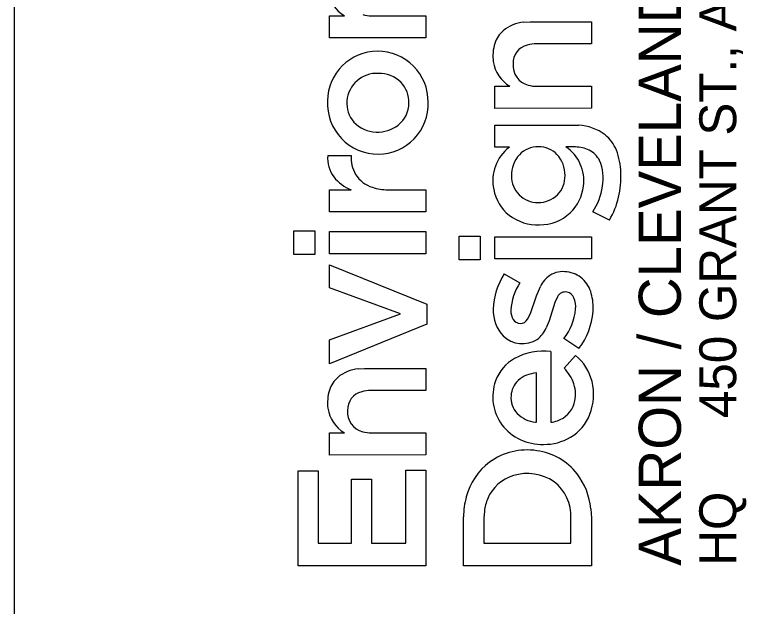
# Model space of a CAD drawing. Extents: x -0.3 to 34, y 0 to 22.
# Drawn here: x 32 to 32.989, y 2.583 to 3.382 of the extents above; entities that cross this region are included whole.
import ezdxf

# ---------------------------------------------------------------- set-up
doc = ezdxf.new("R2010")
doc.units = 0
doc.layers.add('GM_X_Adjacent_County_Text', color=7, linetype='Continuous')
doc.layers.add('GM_X_County', color=7, linetype='Continuous')

msp = doc.modelspace()

# ---------------------------------------------------------------- linework, layer by layer
at = {"layer": 'GM_X_Adjacent_County_Text'}
for p, q in [((32.42542, 3.38066), (32.44552, 3.38071)), ((32.42542, 3.35086), (32.42542, 3.38066)), ((32.48222, 3.38071), (32.55569, 3.38071)), ((32.55569, 3.38071), (32.55571, 3.35096)), ((32.68784, 3.3722), (32.69634, 3.37266)), ((32.69634, 3.37266), (32.77916, 3.37266)), ((32.77916, 3.37266), (32.77917, 3.34287)), ((32.55571, 3.35096), (32.42542, 3.35086)), ((32.77917, 3.34287), (32.70485, 3.3428)), ((32.64888, 3.2855), (32.66897, 3.28555)), ((32.64888, 3.25569), (32.64888, 3.2855)), ((32.70568, 3.28555), (32.77915, 3.28555)), ((32.77915, 3.28555), (32.77917, 3.25579)), ((32.77917, 3.25579), (32.64888, 3.25569)), ((32.6489, 3.20336), (32.64889, 3.23322)), ((32.64889, 3.23322), (32.75236, 3.23322)), ((32.75236, 3.23322), (32.76191, 3.23285)), ((32.66836, 3.20336), (32.6489, 3.20336)), ((32.75763, 3.20356), (32.74487, 3.20361)), ((32.42299, 3.19193), (32.45454, 3.19193)), ((32.42542, 3.14577), (32.45473, 3.14579)), ((32.42542, 3.11593), (32.42542, 3.14577)), ((32.50413, 3.14581), (32.55571, 3.14573)), ((32.55571, 3.14573), (32.55565, 3.11593)), ((32.55565, 3.11593), (32.42542, 3.11593)), ((32.8036, 3.10491), (32.7812, 3.11598)), ((32.37705, 3.05818), (32.37705, 3.09026)), ((32.37705, 3.09026), (32.40543, 3.09026)), ((32.40543, 3.09026), (32.40543, 3.05818)), ((32.42542, 3.05942), (32.42542, 3.08928)), ((32.42542, 3.08928), (32.55571, 3.08928)), ((32.55571, 3.08928), (32.55571, 3.05942)), ((32.60051, 3.05111), (32.60051, 3.08319)), ((32.60051, 3.08319), (32.62889, 3.08319)), ((32.62889, 3.08319), (32.62889, 3.05111)), ((32.64888, 3.05234), (32.64888, 3.0822)), ((32.64888, 3.0822), (32.77917, 3.0822)), ((32.77917, 3.0822), (32.77917, 3.05234)), ((32.40543, 3.05818), (32.37705, 3.05818)), ((32.55571, 3.05942), (32.42542, 3.05942)), ((32.62889, 3.05111), (32.60051, 3.05111)), ((32.77917, 3.05234), (32.64888, 3.05234)), ((32.42542, 3.01327), (32.42542, 3.0446)), ((32.42542, 3.0446), (32.5567, 2.9913)), ((32.66151, 3.03207), (32.68268, 3.02025)), ((32.70483, 3.00258), (32.71036, 3.01526)), ((32.52117, 2.97798), (32.42542, 3.01327)), ((32.69675, 2.97868), (32.70483, 3.00258)), ((32.73342, 3.00101), (32.72985, 2.9933)), ((32.5567, 2.9913), (32.5567, 2.96441)), ((32.72985, 2.9933), (32.72213, 2.96882)), ((32.42542, 2.94294), (32.52117, 2.97798)), ((32.69299, 2.97117), (32.69675, 2.97868)), ((32.72213, 2.96882), (32.71822, 2.95921)), ((32.5567, 2.96441), (32.42542, 2.91086)), ((32.42542, 2.91086), (32.42542, 2.94294)), ((32.76214, 2.93141), (32.74198, 2.94469)), ((32.72453, 2.92747), (32.72463, 2.83195)), ((32.74228, 2.90465), (32.75768, 2.922)), ((32.46439, 2.90397), (32.47289, 2.90443)), ((32.47289, 2.90443), (32.55571, 2.90443)), ((32.55571, 2.90443), (32.55571, 2.87465)), ((32.70489, 2.83182), (32.70489, 2.89834)), ((32.55571, 2.87465), (32.4814, 2.87457)), ((32.70361, 2.83165), (32.70489, 2.83182)), ((32.42542, 2.81728), (32.44552, 2.81733)), ((32.42542, 2.78747), (32.42542, 2.81728)), ((32.48222, 2.81733), (32.55569, 2.81733)), ((32.55569, 2.81733), (32.55571, 2.78756)), ((32.55571, 2.78756), (32.42542, 2.78747)), ((32.38298, 2.63791), (32.38298, 2.76598)), ((32.38298, 2.76598), (32.41012, 2.76598)), ((32.41012, 2.76598), (32.41012, 2.66827)), ((32.52857, 2.66827), (32.52857, 2.76722)), ((32.52857, 2.76722), (32.55571, 2.76722)), ((32.55571, 2.76722), (32.55571, 2.63791)), ((32.45503, 2.66827), (32.45503, 2.75488)), ((32.45503, 2.75488), (32.48218, 2.75488)), ((32.48218, 2.75488), (32.48218, 2.66827)), ((32.63465, 2.71178), (32.63407, 2.7023)), ((32.77847, 2.71497), (32.77917, 2.7021)), ((32.60643, 2.63799), (32.60644, 2.704)), ((32.63407, 2.7023), (32.63407, 2.66838)), ((32.75149, 2.66834), (32.75153, 2.70239)), ((32.77917, 2.7021), (32.77917, 2.638)), ((32.41012, 2.66827), (32.45503, 2.66827)), ((32.48218, 2.66827), (32.52857, 2.66827)), ((32.63407, 2.66838), (32.75149, 2.66834)), ((32.55571, 2.63791), (32.38298, 2.63791)), ((32.77917, 2.638), (32.60643, 2.63799))]:
    msp.add_line(p, q, dxfattribs=at)
for points in [[(32.42542, 3.35086), (32.42542, 3.38066), (32.44552, 3.38071)], [(32.48222, 3.38071), (32.55569, 3.38071), (32.55571, 3.35096), (32.42542, 3.35086)], [(32.68784, 3.3722), (32.69634, 3.37266), (32.77916, 3.37266), (32.77917, 3.34287), (32.70485, 3.3428)], [(32.64888, 3.25569), (32.64888, 3.2855), (32.66897, 3.28555)], [(32.70568, 3.28555), (32.77915, 3.28555), (32.77917, 3.25579), (32.64888, 3.25569)], [(32.66836, 3.20336), (32.6489, 3.20336), (32.64889, 3.23322), (32.75236, 3.23322), (32.76191, 3.23285)], [(32.75763, 3.20356), (32.74487, 3.20361)], [(32.42299, 3.19193), (32.45454, 3.19193)], [(32.50413, 3.14581), (32.55571, 3.14573), (32.55565, 3.11593), (32.42542, 3.11593)], [(32.42542, 3.11593), (32.42542, 3.14577), (32.45473, 3.14579)], [(32.8036, 3.10491), (32.7812, 3.11598)], [(32.66151, 3.03207), (32.68268, 3.02025)], [(32.69299, 2.97117), (32.69675, 2.97868), (32.70483, 3.00258), (32.71036, 3.01526)], [(32.73342, 3.00101), (32.72985, 2.9933), (32.72213, 2.96882), (32.71822, 2.95921)], [(32.76214, 2.93141), (32.74198, 2.94469)], [(32.72453, 2.92747), (32.72463, 2.83195)], [(32.74228, 2.90465), (32.75768, 2.922)], [(32.46439, 2.90397), (32.47289, 2.90443), (32.55571, 2.90443), (32.55571, 2.87465), (32.4814, 2.87457)], [(32.70361, 2.83165), (32.70489, 2.83182), (32.70489, 2.89834)], [(32.42542, 2.78747), (32.42542, 2.81728), (32.44552, 2.81733)], [(32.48222, 2.81733), (32.55569, 2.81733), (32.55571, 2.78756), (32.42542, 2.78747)], [(32.77847, 2.71497), (32.77917, 2.7021), (32.77917, 2.638), (32.60643, 2.63799)], [(32.63465, 2.71178), (32.63407, 2.7023), (32.63407, 2.66838), (32.75149, 2.66834), (32.75153, 2.70239)], [(32.60643, 2.63799), (32.60644, 2.704)]]:
    msp.add_lwpolyline(points, dxfattribs=at)
for points in [[(32.37705, 3.05818), (32.37705, 3.09026), (32.40543, 3.09026), (32.40543, 3.05818)], [(32.42542, 3.05942), (32.42542, 3.08928), (32.55571, 3.08928), (32.55571, 3.05942)], [(32.60051, 3.05111), (32.60051, 3.08319), (32.62889, 3.08319), (32.62889, 3.05111)], [(32.64888, 3.05234), (32.64888, 3.0822), (32.77917, 3.0822), (32.77917, 3.05234)], [(32.42542, 2.91086), (32.42542, 2.94294), (32.52117, 2.97798), (32.42542, 3.01327), (32.42542, 3.0446), (32.5567, 2.9913), (32.5567, 2.96441)], [(32.38298, 2.63791), (32.38298, 2.76598), (32.41012, 2.76598), (32.41012, 2.66827), (32.45503, 2.66827), (32.45503, 2.75488), (32.48218, 2.75488), (32.48218, 2.66827), (32.52857, 2.66827), (32.52857, 2.76722), (32.55571, 2.76722), (32.55571, 2.63791)]]:
    msp.add_lwpolyline(points, close=True, dxfattribs=at)
for centre, radius, start, end in [((32.47027, 3.42141), 0.04763, 188.96462, 238.69865), ((32.47027, 3.42141), 0.04763, 188.96462, 238.69865), ((32.48183, 3.42286), 0.04215, 254.08913, 270.52838), ((32.48183, 3.42286), 0.04215, 254.08913, 270.52838), ((32.69216, 3.32251), 0.04988, 94.97056, 130.22484), ((32.69216, 3.32251), 0.04988, 94.97056, 130.22484), ((32.68694, 3.33085), 0.04016, 132.22383, 161.68229), ((32.68694, 3.33085), 0.04016, 132.22383, 161.68229), ((32.70217, 3.32642), 0.05602, 162.27398, 187.79173), ((32.70217, 3.32642), 0.05602, 162.27398, 187.79173), ((32.70453, 3.29679), 0.04601, 89.60515, 105.33026), ((32.70453, 3.29679), 0.04601, 89.60515, 105.33026), ((32.49014, 3.26543), 0.0674, 89.84756, 179.64047), ((32.49014, 3.26543), 0.0674, 89.84756, 179.64047), ((32.49057, 3.26474), 0.0681, 359.54009, 90.21138), ((32.49057, 3.26474), 0.0681, 359.54009, 90.21138), ((32.69828, 3.31689), 0.02498, 103.68683, 182.21395), ((32.69828, 3.31689), 0.02498, 103.68683, 182.21395), ((32.69372, 3.32624), 0.04763, 188.96462, 238.69865), ((32.69372, 3.32624), 0.04763, 188.96462, 238.69865), ((32.7008, 3.31381), 0.02757, 175.58441, 255.13816), ((32.7008, 3.31381), 0.02757, 175.58441, 255.13816), ((32.48923, 3.26263), 0.0404, 87.04809, 175.57259), ((32.48923, 3.26263), 0.0404, 87.04809, 175.57259), ((32.49204, 3.25999), 0.04299, 45.84264, 90.98008), ((32.49204, 3.25999), 0.04299, 45.84264, 90.98008), ((32.49458, 3.26421), 0.03821, 357.88569, 44.15902), ((32.49458, 3.26421), 0.03821, 357.88569, 44.15902), ((32.70529, 3.32769), 0.04215, 254.08913, 270.52838), ((32.70529, 3.32769), 0.04215, 254.08913, 270.52838), ((32.49083, 3.26209), 0.06819, 176.8344, 270.40384), ((32.49083, 3.26209), 0.06819, 176.8344, 270.40384), ((32.48729, 3.2625), 0.03848, 175.15378, 221.14706), ((32.48729, 3.2625), 0.03848, 175.15378, 221.14706), ((32.49123, 3.26139), 0.06749, 270.06243, 2.37759), ((32.49123, 3.26139), 0.06749, 270.06243, 2.37759), ((32.49446, 3.26318), 0.0383, 308.28936, 359.43468), ((32.49446, 3.26318), 0.0383, 308.28936, 359.43468), ((32.48919, 3.26607), 0.04228, 223.09994, 268.80895), ((32.48919, 3.26607), 0.04228, 223.09994, 268.80895), ((32.49096, 3.2679), 0.04418, 266.56515, 308.06078), ((32.49096, 3.2679), 0.04418, 266.56515, 308.06078), ((32.75907, 3.16789), 0.06503, 53.40344, 87.49062), ((32.75907, 3.16789), 0.06503, 53.40344, 87.49062), ((32.76517, 3.18039), 0.05141, 21.60748, 50.5577), ((32.76517, 3.18039), 0.05141, 21.60748, 50.5577), ((32.70292, 3.15813), 0.05692, 127.37482, 192.22468), ((32.70292, 3.15813), 0.05692, 127.37482, 192.22468), ((32.70693, 3.16927), 0.0346, 88.47302, 136.42562), ((32.70693, 3.16927), 0.0346, 88.47302, 136.42562), ((32.70814, 3.16963), 0.03424, 44.27195, 90.47623), ((32.70814, 3.16963), 0.03424, 44.27195, 90.47623), ((32.71421, 3.15829), 0.05472, 352.1125, 55.92295), ((32.71421, 3.15829), 0.05472, 352.1125, 55.92295), ((32.75666, 3.15725), 0.04633, 65.01687, 88.8011), ((32.75666, 3.15725), 0.04633, 65.01687, 88.8011), ((32.71141, 3.16602), 0.0401, 137.46739, 182.33237), ((32.71141, 3.16602), 0.0401, 137.46739, 182.33237), ((32.70368, 3.166), 0.03996, 358.57141, 43.53765), ((32.70368, 3.166), 0.03996, 358.57141, 43.53765), ((32.7626, 3.17155), 0.03085, 26.26808, 63.80301), ((32.7626, 3.17155), 0.03085, 26.26808, 63.80301), ((32.73069, 3.16714), 0.08835, 1.15143, 21.3627), ((32.73069, 3.16714), 0.08835, 1.15143, 21.3627), ((32.46616, 3.18882), 0.04329, 175.87313, 216.34747), ((32.46616, 3.18882), 0.04329, 175.87313, 216.34747), ((32.50087, 3.18948), 0.04639, 176.9688, 209.60636), ((32.50087, 3.18948), 0.04639, 176.9688, 209.60636), ((32.73565, 3.16154), 0.05953, 349.30734, 23.43071), ((32.73565, 3.16154), 0.05953, 349.30734, 23.43071), ((32.49514, 3.18814), 0.04079, 211.94466, 253.2028), ((32.49514, 3.18814), 0.04079, 211.94466, 253.2028), ((32.70645, 3.1637), 0.03511, 178.88208, 271.08374), ((32.70645, 3.1637), 0.03511, 178.88208, 271.08374), ((32.70818, 3.16404), 0.03546, 268.27882, 1.55016), ((32.70818, 3.16404), 0.03546, 268.27882, 1.55016), ((32.70538, 3.16244), 0.11383, 329.6388, 3.25998), ((32.70538, 3.16244), 0.11383, 329.6388, 3.25998), ((32.47466, 3.19716), 0.05511, 218.09809, 248.7907), ((32.47466, 3.19716), 0.05511, 218.09809, 248.7907), ((32.50465, 3.2165), 0.07069, 252.46555, 269.57296), ((32.50465, 3.2165), 0.07069, 252.46555, 269.57296), ((32.70463, 3.15696), 0.05837, 190.75182, 231.28919), ((32.70463, 3.15696), 0.05837, 190.75182, 231.28919), ((32.70988, 3.15708), 0.05887, 313.74196, 353.8554), ((32.70988, 3.15708), 0.05887, 313.74196, 353.8554), ((32.70738, 3.16334), 0.08771, 327.31495, 351.57478), ((32.70738, 3.16334), 0.08771, 327.31495, 351.57478), ((32.70954, 3.15901), 0.06051, 269.6361, 312.70877), ((32.70954, 3.15901), 0.06051, 269.6361, 312.70877), ((32.70632, 3.16112), 0.06269, 232.46061, 272.59022), ((32.70632, 3.16112), 0.06269, 232.46061, 272.59022), ((32.7406, 3.0026), 0.03263, 80.17192, 122.51969), ((32.7406, 3.0026), 0.03263, 80.17192, 122.51969), ((32.73636, 2.98258), 0.08973, 146.53104, 178.7571), ((32.73636, 2.98258), 0.08973, 146.53104, 178.7571), ((32.74661, 2.99713), 0.04053, 125.51182, 153.41595), ((32.74661, 2.99713), 0.04053, 125.51182, 153.41595), ((32.74278, 2.99824), 0.03667, 47.79344, 84.68918), ((32.74278, 2.99824), 0.03667, 47.79344, 84.68918), ((32.73788, 2.9946), 0.04267, 14.9966, 46.20632), ((32.73788, 2.9946), 0.04267, 14.9966, 46.20632), ((32.74519, 2.9789), 0.07495, 146.51121, 176.91007), ((32.74519, 2.9789), 0.07495, 146.51121, 176.91007), ((32.74384, 2.99631), 0.01143, 76.66094, 155.7053), ((32.74384, 2.99631), 0.01143, 76.66094, 155.7053), ((32.74397, 2.99511), 0.01256, 21.5098, 78.52618), ((32.74397, 2.99511), 0.01256, 21.5098, 78.52618), ((32.71044, 2.98674), 0.07121, 355.83062, 15.39138), ((32.71044, 2.98674), 0.07121, 355.83062, 15.39138), ((32.72592, 2.98766), 0.03209, 354.57264, 22.06805), ((32.72592, 2.98766), 0.03209, 354.57264, 22.06805), ((32.69666, 2.98238), 0.05005, 177.53659, 222.79318), ((32.69666, 2.98238), 0.05005, 177.53659, 222.79318), ((32.6931, 2.98233), 0.02276, 178.47474, 211.08679), ((32.6931, 2.98233), 0.02276, 178.47474, 211.08679), ((32.68248, 2.99149), 0.0757, 321.81101, 354.79685), ((32.68248, 2.99149), 0.0757, 321.81101, 354.79685), ((32.68952, 2.9882), 0.09219, 321.9777, 355.87384), ((32.68952, 2.9882), 0.09219, 321.9777, 355.87384), ((32.68331, 2.9767), 0.01148, 212.23676, 268.37769), ((32.68331, 2.9767), 0.01148, 212.23676, 268.37769), ((32.68342, 2.97589), 0.01067, 267.71603, 333.73375), ((32.68342, 2.97589), 0.01067, 267.71603, 333.73375), ((32.68098, 2.9758), 0.04077, 308.08772, 335.98736), ((32.68098, 2.9758), 0.04077, 308.08772, 335.98736), ((32.68599, 2.97535), 0.0375, 225.98539, 302.47965), ((32.68599, 2.97535), 0.0375, 225.98539, 302.47965), ((32.7152, 2.84414), 0.08384, 83.61499, 118.28755), ((32.7152, 2.84414), 0.08384, 83.61499, 118.28755), ((32.70239, 2.86906), 0.05583, 118.83082, 160.62438), ((32.70239, 2.86906), 0.05583, 118.83082, 160.62438), ((32.71744, 2.87167), 0.06443, 13.53365, 51.36148), ((32.71744, 2.87167), 0.06443, 13.53365, 51.36148), ((32.46871, 2.85428), 0.04988, 94.96958, 130.22249), ((32.46871, 2.85428), 0.04988, 94.96958, 130.22249), ((32.70785, 2.85609), 0.04235, 94.00805, 130.88169), ((32.70785, 2.85609), 0.04235, 94.00805, 130.88169), ((32.70378, 2.86556), 0.05486, 19.03571, 45.44059), ((32.70378, 2.86556), 0.05486, 19.03571, 45.44059), ((32.46348, 2.86263), 0.04015, 132.22192, 161.68183), ((32.46348, 2.86263), 0.04015, 132.22192, 161.68183), ((32.71041, 2.86612), 0.06437, 160.52012, 215.78311), ((32.71041, 2.86612), 0.06437, 160.52012, 215.78311), ((32.70048, 2.86628), 0.02985, 132.98507, 177.179), ((32.70048, 2.86628), 0.02985, 132.98507, 177.179), ((32.70635, 2.86921), 0.07579, 339.3542, 13.37853), ((32.70635, 2.86921), 0.07579, 339.3542, 13.37853), ((32.71069, 2.8697), 0.047, 344.60586, 17.007), ((32.71069, 2.8697), 0.047, 344.60586, 17.007), ((32.47872, 2.85819), 0.05601, 162.27355, 187.79185), ((32.47872, 2.85819), 0.05601, 162.27355, 187.79185), ((32.47482, 2.84867), 0.02498, 103.68646, 182.21874), ((32.47482, 2.84867), 0.02498, 103.68646, 182.21874), ((32.48108, 2.82856), 0.04601, 89.60494, 105.3284), ((32.48108, 2.82856), 0.04601, 89.60494, 105.3284), ((32.7017, 2.86503), 0.03115, 175.00126, 223.28301), ((32.7017, 2.86503), 0.03115, 175.00126, 223.28301), ((32.7224, 2.86715), 0.03504, 288.00773, 343.55078), ((32.7224, 2.86715), 0.03504, 288.00773, 343.55078), ((32.47026, 2.85802), 0.04762, 188.96199, 238.70369), ((32.47026, 2.85802), 0.04762, 188.96199, 238.70369), ((32.47735, 2.84558), 0.02756, 175.58538, 255.14386), ((32.47735, 2.84558), 0.02756, 175.58538, 255.14386), ((32.70891, 2.87363), 0.04231, 225.06188, 262.79738), ((32.70891, 2.87363), 0.04231, 225.06188, 262.79738), ((32.71894, 2.8652), 0.0626, 300.94269, 338.73225), ((32.71894, 2.8652), 0.0626, 300.94269, 338.73225), ((32.71253, 2.87054), 0.06872, 217.74516, 271.65431), ((32.71253, 2.87054), 0.06872, 217.74516, 271.65431), ((32.72474, 2.85216), 0.02021, 269.7003, 294.8711), ((32.72474, 2.85216), 0.02021, 269.7003, 294.8711), ((32.48183, 2.85948), 0.04215, 254.09162, 270.52835), ((32.48183, 2.85948), 0.04215, 254.09162, 270.52835), ((32.71549, 2.87241), 0.07056, 269.20477, 300.33412), ((32.71549, 2.87241), 0.07056, 269.20477, 300.33412), ((32.69229, 2.70792), 0.08641, 81.19402, 125.99844), ((32.69229, 2.70792), 0.08641, 81.19402, 125.99844), ((32.69458, 2.71132), 0.08272, 37.85208, 82.40204), ((32.69458, 2.71132), 0.08272, 37.85208, 82.40204), ((32.69387, 2.70893), 0.08654, 127.23621, 165.14796), ((32.69387, 2.70893), 0.08654, 127.23621, 165.14796), ((32.68893, 2.70782), 0.05398, 106.18808, 157.38609), ((32.68893, 2.70782), 0.05398, 106.18808, 157.38609), ((32.69279, 2.69862), 0.06389, 55.67272, 107.20935), ((32.69279, 2.69862), 0.06389, 55.67272, 107.20935), ((32.68586, 2.70567), 0.09308, 5.73329, 37.30396), ((32.68586, 2.70567), 0.09308, 5.73329, 37.30396), ((32.69291, 2.70499), 0.05867, 357.46616, 52.26647), ((32.69291, 2.70499), 0.05867, 357.46616, 52.26647), ((32.71426, 2.70281), 0.10783, 164.7861, 179.37039), ((32.71426, 2.70281), 0.10783, 164.7861, 179.37039), ((32.69829, 2.70389), 0.06412, 157.35705, 172.92755), ((32.69829, 2.70389), 0.06412, 157.35705, 172.92755)]:
    msp.add_arc(centre, radius, start, end, dxfattribs=at)
at = {"layer": 'GM_X_County'}
msp.add_line((32, 0.5), (32, 21.5), dxfattribs=at)

# ---------------------------------------------------------------- texts
at = {"layer": 'GM_X_Adjacent_County_Text'}
for s, height, p in [('450 GRANT ST., AKRON, OH  44311', 0.0498462, (32.97489, 2.83738)), ('AKRON / CLEVELAND / COLUMBUS', 0.056969, (32.90012, 2.638)), ('HQ ', 0.049846, (32.97489, 2.638))]:
    msp.add_text(s, height=height, rotation=90, dxfattribs=at).set_placement(p)

doc.saveas('drawing.dxf')
